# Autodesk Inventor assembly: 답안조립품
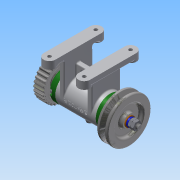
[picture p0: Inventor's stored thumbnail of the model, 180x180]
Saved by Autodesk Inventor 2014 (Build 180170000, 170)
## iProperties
Created: 2015-11
Part Number: 답안조립품
Document SubType Name: Assembly
Designer: 103-19
Author: 103-19
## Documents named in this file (15)
- C:\Users\103-19\Desktop\451110V1054\답안조립품.iam
- C:\Users\103-19\Desktop\451110V1054\1-본체.ipt
- C:\Users\103-19\Desktop\451110V1054\베어링 15 x 32 x 9.ipt
- C:\Users\103-19\Desktop\451110V1054\축.ipt
- C:\Users\103-19\Desktop\451110V1054\키 3 x 3 x 12.ipt
- C:\Users\103-19\Desktop\451110V1054\V벨트풀리.ipt
- C:\Users\103-19\Desktop\451110V1054\스퍼기어.ipt
- C:\Users\103-19\Desktop\451110V1054\커버.ipt
- C:\Users\103-19\Desktop\451110V1054\볼트 M4 x 12.ipt
- C:\Users\103-19\Desktop\451110V1054\오일 실 15 25 7.ipt
- C:\Users\103-19\Desktop\451110V1054\와셔 8x17.ipt
- C:\Users\103-19\Desktop\451110V1054\스프링와셔 8.ipt
- C:\Users\103-19\Desktop\451110V1054\너트 M 8.ipt
- C:\Users\103-19\Desktop\451110V1054\볼트 M 6 x 8.ipt
- C:\Users\103-19\Desktop\451110V1054\와셔 6x11.5.ipt
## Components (12 placed, 4 different names)
1. 1-본체:1
2. KS B 2023 6002 - 15 x 32 x 9:1
3. KS B 2023 6002 - 15 x 32 x 9:2
4. V벨트풀리:1 — 각도:3
5. ISO 4762 M4 x 12:1
6. ISO 4762 M4 x 12:2
7. ISO 4762 M4 x 12:3
8. ISO 4762 M4 x 12:4
9. ISO 4762 M4 x 12:5
10. ISO 4762 M4 x 12:6
11. ISO 4762 M4 x 12:7
12. ISO 4762 M4 x 12:8
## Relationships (1: Angle 1)
- 각도:3 [Angle]: V벨트풀리:1
